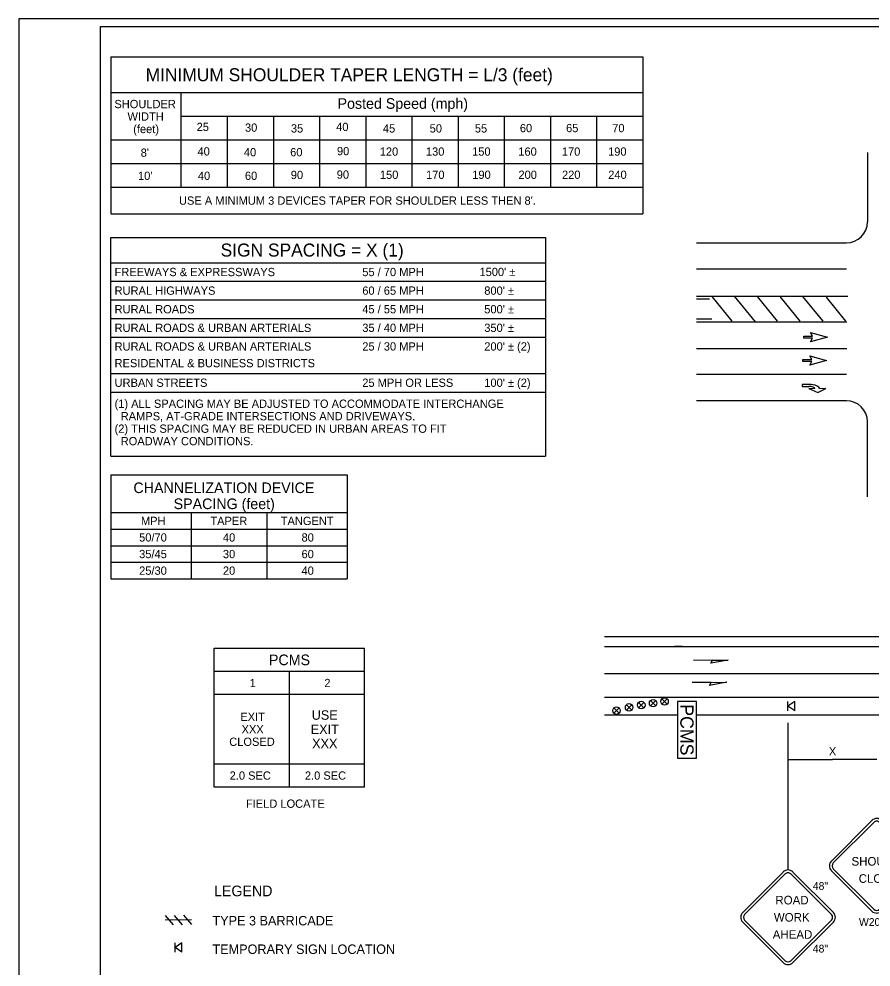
# Model space of a CAD drawing. Extents: x 99988 to 100172, y 99995 to 100047.
# Drawn here: x 99999.31 to 100006.52, y 100002.41 to 100010.44 of the extents above; entities that cross this region are included whole.
import ezdxf

# ---------------------------------------------------------------- set-up
doc = ezdxf.new("R2010")
doc.units = 0
for name, color, linetype in [('Default', 7, 'Continuous'), ('Level 15', 7, 'Continuous'), ('Level 20', 7, 'Continuous'), ('RD_MK_TrafficArrowType1SNew', 7, 'Continuous'), ('RD_MK_TrafficArrowType2RNew', 7, 'Continuous'), ('SH_DE_DetailBody1Text', 7, 'Continuous'), ('SH_DE_DetailHeading2Text', 7, 'Continuous'), ('SH_GI_PlotLimits', 7, 'Continuous'), ('SH_GI_SheetBorder', 7, 'Continuous'), ('SH_GI_TrafficMvmntArrowRt1Lane', 7, 'Continuous'), ('SH_TI_ChanSpacing25to70Note', 7, 'Continuous'), ('SH_TI_MinTaperLength25to35Note', 7, 'Continuous'), ('SH_TI_SignSpacing35to70Note', 7, 'Continuous'), ('TR_SN_WarningSigns', 7, 'Continuous'), ('TR_WZ_BarricadeType3', 7, 'Continuous'), ('TR_WZ_PortableChangeMessageSign', 7, 'Continuous'), ('TR_WZ_WorkZoneDetails', 7, 'Continuous')]:
    doc.layers.add(name, color=color, linetype=linetype)

# ---------------------------------------------------------------- blocks, each defined once
blk = doc.blocks.new('W20-301')
at = {"layer": 'TR_SN_WarningSigns'}
for p, q in [((-0.511, 0.688), (-0.054, 1.145)), ((-0.49, 0.666), (-0.033, 1.123)), ((0.033, 1.123), (0.49, 0.666)), ((0.054, 1.145), (0.511, 0.688)), ((-0.054, 0.123), (-0.511, 0.579)), ((-0.033, 0.144), (-0.49, 0.601)), ((0.49, 0.601), (0.033, 0.144)), ((0.511, 0.579), (0.054, 0.123))]:
    blk.add_line(p, q, dxfattribs=at)
for centre, radius, start, end in [((0, 1.091), 0.0769, 44.9963, 134.9997), ((0, 1.091), 0.0462, 44.9963, 134.9997), ((-0.457, 0.634), 0.0769, 134.9966, 224.9936), ((-0.457, 0.634), 0.0462, 134.9966, 224.9936), ((0.457, 0.634), 0.0462, 314.9994, 44.9948), ((0.457, 0.634), 0.0769, 314.9994, 44.9948), ((0, 0.177), 0.0769, 225, 314.9996), ((0, 0.177), 0.0462, 225, 314.9996)]:
    blk.add_arc(centre, radius, start, end, dxfattribs=at)
for s, height, p in [('48"', 0.0848, (0.282, 0.945)), ('SHOULDER', 0.0969, (-0.284, 0.636)), ('CLOSED', 0.0969, (-0.203, 0.442)), ('48"', 0.0848, (0.282, 0.238)), ('W20-301', 0.0875, (-0.2, -0.044))]:
    blk.add_text(s, height=height, dxfattribs=at).set_placement(p)

msp = doc.modelspace()

# ---------------------------------------------------------------- linework, layer by layer
at = {"layer": 'Default'}
for p, q in [((100004.2658, 100004.8971), (100015.1319, 100004.8971)), ((100004.7968, 100004.6379), (100004.7516, 100004.6831)), ((100004.7968, 100004.6831), (100004.7516, 100004.6379)), ((100004.3903, 100004.5605), (100004.345, 100004.6057)), ((100004.3903, 100004.6057), (100004.345, 100004.5605)), ((100004.4973, 100004.5874), (100004.452, 100004.6327)), ((100004.4973, 100004.6327), (100004.452, 100004.5874)), ((100004.5995, 100004.6076), (100004.5543, 100004.6529)), ((100004.5995, 100004.6529), (100004.5543, 100004.6076)), ((100004.7003, 100004.6235), (100004.6551, 100004.6687)), ((100004.7003, 100004.6687), (100004.6551, 100004.6235)), ((100005.8761, 100004.6609), (100005.8183, 100004.6206)), ((100005.8183, 100004.5804), (100005.8183, 100004.6609)), ((100005.8761, 100004.5804), (100005.8183, 100004.6206)), ((100005.8761, 100004.5804), (100005.8761, 100004.6609)), ((100000.6909, 100002.6181), (100000.6331, 100002.5778)), ((100000.6331, 100002.5376), (100000.6331, 100002.6181)), ((100000.6909, 100002.5376), (100000.6909, 100002.6181)), ((100000.6909, 100002.5376), (100000.6331, 100002.5778))]:
    msp.add_line(p, q, dxfattribs=at)
for centre in [(100004.6777, 100004.6461), (100004.7742, 100004.6605), (100004.3677, 100004.5831), (100004.4746, 100004.6101), (100004.5769, 100004.6302)]:
    msp.add_circle(centre, 0.032, dxfattribs=at)
at = {"layer": 'Level 15'}
for p in [(100005.819, 100004.1687), (100006.569, 100004.1687)]:
    msp.add_line(p, (100006.194, 100004.1687), dxfattribs=at)
at = {"layer": 'RD_MK_TrafficArrowType1SNew'}
for points in [[(100005.9514, 100007.7523), (100006.0264, 100007.7523), (100006.0097, 100007.7835), (100006.1514, 100007.744), (100006.0097, 100007.7044), (100006.0264, 100007.7356), (100005.9514, 100007.7356)], [(100005.9443, 100007.5545), (100006.0193, 100007.5545), (100006.0026, 100007.5857), (100006.1443, 100007.5462), (100006.0026, 100007.5066), (100006.0193, 100007.5378), (100005.9443, 100007.5378)]]:
    msp.add_lwpolyline(points, close=True, dxfattribs=at)
at = {"layer": 'RD_MK_TrafficArrowType2RNew'}
msp.add_line((100005.9958, 100007.3435), (100005.9958, 100007.3435), dxfattribs=at)
for points in [[(100005.9958, 100007.3435), (100005.9374, 100007.3435), (100005.9374, 100007.3268), (100005.9958, 100007.3268)], [(100006.0458, 100007.306), (100005.9958, 100007.3102), (100006.0708, 100007.2768), (100006.1374, 100007.3102), (100006.0874, 100007.306)]]:
    msp.add_lwpolyline(points, dxfattribs=at)
for major_axis, ratio, end_param in [((0.0917, 0), 0.40879, 1.570662), ((0.05, 0), 0.41611, 1.570668)]:
    msp.add_ellipse((100005.9958, 100007.306), major_axis=major_axis, ratio=ratio, start_param=0, end_param=end_param, dxfattribs=at)
at = {"layer": 'SH_GI_PlotLimits'}
msp.add_lwpolyline([(99999.3125, 99999.9375), (100015.8125, 99999.9375), (100015.8125, 100010.4375), (99999.3125, 100010.4375)], close=True, dxfattribs=at)
at = {"layer": 'SH_GI_SheetBorder'}
for q in [(100000, 100000), (100015.75, 100010.375)]:
    msp.add_line((100000, 100010.375), q, dxfattribs=at)
at = {"layer": 'SH_GI_TrafficMvmntArrowRt1Lane'}
for p, q in [((100005.1801, 100005.0095), (100005.0194, 100005.0074)), ((100005.1691, 100004.8221), (100005.0084, 100004.82))]:
    msp.add_line(p, q, dxfattribs=at)
for points in [[(100005.3111, 100005.0113), (100005.1656, 100004.9836), (100005.1801, 100005.0095)], [(100005.3001, 100004.8239), (100005.1546, 100004.7962), (100005.1691, 100004.8221)]]:
    msp.add_lwpolyline(points, close=True, dxfattribs=at)
at = {"layer": 'SH_TI_ChanSpacing25to70Note'}
for p, q in [((100000.0888, 100006.5798), (100000.0888, 100005.6977)), ((100000.0888, 100006.5798), (100002.0888, 100006.5798)), ((100002.0888, 100006.5798), (100002.0888, 100005.6977)), ((100000.0888, 100006.2592), (100002.0888, 100006.2592)), ((100000.7714, 100005.6977), (100000.7714, 100006.2592)), ((100001.4135, 100005.6977), (100001.4135, 100006.2592)), ((100000.0888, 100006.1188), (100002.0888, 100006.1188)), ((100000.0888, 100005.9785), (100002.0888, 100005.9785)), ((100000.0888, 100005.8381), (100002.0888, 100005.8381)), ((100000.0888, 100005.6977), (100002.0888, 100005.6977))]:
    msp.add_line(p, q, dxfattribs=at)
at = {"layer": 'SH_TI_MinTaperLength25to35Note'}
for p, q in [((100000.0904, 100010.1177), (100004.5904, 100010.1177)), ((100000.0904, 100010.1177), (100000.0904, 100009.4074)), ((100004.5904, 100010.1177), (100004.5904, 100009.4074)), ((100000.0904, 100009.8145), (100004.5904, 100009.8145)), ((100000.6835, 100009.4074), (100000.6835, 100009.8145)), ((100000.6835, 100009.6145), (100004.5904, 100009.6145)), ((100001.0742, 100009.6145), (100001.0742, 100009.4074)), ((100001.4649, 100009.6145), (100001.4649, 100009.4074)), ((100001.8556, 100009.6145), (100001.8556, 100009.4074)), ((100002.2463, 100009.6145), (100002.2463, 100009.4074)), ((100002.637, 100009.6145), (100002.637, 100009.4074)), ((100003.0277, 100009.6145), (100003.0277, 100009.4074)), ((100003.4183, 100009.6145), (100003.4183, 100009.4074)), ((100003.809, 100009.6145), (100003.809, 100009.4074)), ((100004.1996, 100009.6145), (100004.1996, 100009.4074)), ((100000.0904, 100009.4145), (100004.5904, 100009.4145)), ((100000.0904, 100009.4074), (100000.0904, 100008.7876)), ((100000.6835, 100009.0128), (100000.6835, 100009.4074)), ((100001.0742, 100009.4074), (100001.0742, 100009.0128)), ((100001.4649, 100009.4074), (100001.4649, 100009.0128)), ((100001.8556, 100009.4074), (100001.8556, 100009.0128)), ((100002.2463, 100009.4074), (100002.2463, 100009.0128)), ((100002.637, 100009.4074), (100002.637, 100009.0128)), ((100003.0277, 100009.4074), (100003.0277, 100009.0128)), ((100003.4183, 100009.4074), (100003.4183, 100009.0128)), ((100003.809, 100009.4074), (100003.809, 100009.0128)), ((100004.1996, 100009.4074), (100004.1996, 100009.0128)), ((100004.5904, 100009.4074), (100004.5904, 100008.7876)), ((100000.0904, 100009.2128), (100004.5904, 100009.2128)), ((100000.0904, 100009.0128), (100004.5904, 100009.0128)), ((100000.0904, 100008.7876), (100004.5904, 100008.7876))]:
    msp.add_line(p, q, dxfattribs=at)
at = {"layer": 'SH_TI_SignSpacing35to70Note'}
for p, q in [((100000.0904, 100008.3742), (100003.7659, 100008.3742)), ((100000.0904, 100008.2167), (100003.7659, 100008.2167)), ((100000.0904, 100008.0593), (100003.7659, 100008.0593)), ((100000.0904, 100007.9019), (100003.7659, 100007.9019)), ((100000.0904, 100007.7445), (100003.7659, 100007.7445)), ((100000.0904, 100007.4371), (100003.7659, 100007.4371)), ((100000.0904, 100007.2797), (100003.7659, 100007.2797)), ((100000.0904, 100006.736), (100003.7659, 100006.736))]:
    msp.add_line(p, q, dxfattribs=at)
msp.add_lwpolyline([(100000.0904, 100006.736), (100000.0904, 100008.5887), (100003.7659, 100008.5887), (100003.7659, 100006.736)], dxfattribs=at)
at = {"layer": 'TR_SN_WarningSigns'}
for p, q in [((100005.4355, 100002.8742), (100005.7782, 100003.2168)), ((100005.4519, 100002.8579), (100005.7945, 100003.2005)), ((100005.8435, 100003.2005), (100006.1862, 100002.8578)), ((100005.8598, 100003.2168), (100006.2025, 100002.8742)), ((100005.7782, 100002.4499), (100005.4355, 100002.7926)), ((100005.7945, 100002.4662), (100005.4519, 100002.8089)), ((100006.1862, 100002.8089), (100005.8435, 100002.4662)), ((100006.2025, 100002.7926), (100005.8598, 100002.4499))]:
    msp.add_line(p, q, dxfattribs=at)
for centre, radius, start, end in [((100005.819, 100003.1761), 0.0577, 44.99628, 134.99965), ((100005.819, 100003.1761), 0.0346, 44.99628, 134.99965), ((100005.4763, 100002.8334), 0.0577, 134.99658, 224.99358), ((100005.4763, 100002.8334), 0.0346, 134.99658, 224.99358), ((100006.1617, 100002.8334), 0.0346, 314.99936, 44.99485), ((100006.1617, 100002.8334), 0.0577, 314.99936, 44.99485), ((100005.819, 100002.4907), 0.0577, 225, 314.99958), ((100005.819, 100002.4907), 0.0346, 225, 314.99958)]:
    msp.add_arc(centre, radius, start, end, dxfattribs=at)
at = {"layer": 'TR_WZ_BarricadeType3'}
for p, q in [((100000.5483, 100002.849), (100000.6158, 100002.7703)), ((100000.6268, 100002.8496), (100000.6943, 100002.7709)), ((100000.7053, 100002.8503), (100000.7728, 100002.7716)), ((100000.7725, 100002.8112), (100000.5487, 100002.8093))]:
    msp.add_line(p, q, dxfattribs=at)
at = {"layer": 'TR_WZ_PortableChangeMessageSign'}
msp.add_lwpolyline([(100004.8836, 100004.6608), (100004.8836, 100004.1808), (100005.0436, 100004.1808), (100005.0436, 100004.6608)], close=True, dxfattribs=at)
at = {"layer": 'TR_WZ_WorkZoneDetails'}
for p, q in [((100006.4912, 100009.3085), (100006.4912, 100008.7205)), ((100005.0448, 100008.5417), (100006.3124, 100008.5417)), ((100006.3124, 100008.32), (100005.0448, 100008.32)), ((100006.017, 100008.089), (100005.0448, 100008.089)), ((100005.1558, 100008.0659), (100005.0448, 100008.0659)), ((100005.1736, 100008.0872), (100005.3426, 100007.8804)), ((100005.3632, 100008.0907), (100005.541, 100007.8729)), ((100005.5568, 100008.0892), (100005.7274, 100007.8804)), ((100005.749, 100008.0895), (100005.9197, 100007.8804)), ((100005.9419, 100008.0889), (100006.1121, 100007.8804)), ((100006.3239, 100008.089), (100006.017, 100008.089)), ((100006.1402, 100008.0815), (100006.3045, 100007.8804)), ((100005.1752, 100007.8957), (100005.0448, 100007.8957)), ((100005.0448, 100007.8729), (100006.3159, 100007.8729)), ((100005.0448, 100007.6494), (100006.3159, 100007.6494)), ((100006.3124, 100007.4277), (100005.0448, 100007.4277)), ((100006.3124, 100007.206), (100005.0448, 100007.206)), ((100006.4912, 100006.3918), (100006.4912, 100007.0272)), ((100004.2658, 100005.2089), (100015.1308, 100005.2089)), ((100000.964, 100005.1105), (100002.2371, 100005.1105)), ((100000.964, 100003.9353), (100000.964, 100005.1105)), ((100002.2371, 100003.9353), (100002.2371, 100005.1105)), ((100004.2658, 100005.1256), (100015.1308, 100005.1256)), ((100004.9223, 100005.1256), (100004.8592, 100005.1256)), ((100002.2371, 100004.9146), (100000.964, 100004.9146)), ((100001.6006, 100003.9353), (100001.6006, 100004.9146)), ((100002.2371, 100004.7188), (100000.964, 100004.7188)), ((100004.2658, 100004.6961), (100009.937, 100004.6961)), ((100004.2658, 100004.5463), (100004.8819, 100004.5463)), ((100005.0504, 100004.5463), (100011.3395, 100004.5463)), ((100005.819, 100003.2337), (100005.819, 100004.4804)), ((100000.964, 100004.1311), (100002.2371, 100004.1311)), ((100002.2371, 100003.9353), (100000.964, 100003.9353))]:
    msp.add_line(p, q, dxfattribs=at)
for centre, start, end in [((100006.3124, 100008.7205), 270, 0), ((100006.3124, 100007.0273), 0, 90)]:
    msp.add_arc(centre, 0.1788, start, end, dxfattribs=at)

# ---------------------------------------------------------------- block references
at = {"layer": 'TR_WZ_WorkZoneDetails', "xscale": 0.7500000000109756, "yscale": 0.7500000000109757}
msp.add_blockref('W20-301', (100006.569, 100002.7937), dxfattribs=at)

# ---------------------------------------------------------------- texts
at = {"layer": 'Level 20'}
msp.add_text('X', height=0.07, rotation=360, dxfattribs=at).set_placement((100006.1643, 100004.2037))
at = {"layer": 'SH_DE_DetailBody1Text'}
for s, height, p in [('PCMS', 0.09, (100001.4272, 100004.9676)), ('1', 0.07, (100001.2643, 100004.7817)), ('2', 0.07, (100001.8962, 100004.7817)), ('EXIT', 0.07, (100001.1852, 100004.4955)), ('USE', 0.08, (100001.7891, 100004.5056)), ('XXX', 0.07, (100001.1958, 100004.3899)), ('EXIT', 0.08, (100001.7808, 100004.3849)), ('CLOSED', 0.07, (100001.0915, 100004.2844)), ('XXX', 0.08, (100001.7928, 100004.2643)), ('2.0 SEC', 0.07, (100001.0949, 100003.9982)), ('2.0 SEC', 0.07, (100001.7315, 100003.9982)), ('FIELD LOCATE', 0.07, (100001.2329, 100003.7603)), ('TYPE 3 BARRICADE', 0.08, (100000.9494, 100002.7647)), ('TEMPORARY SIGN LOCATION', 0.08, (100000.9494, 100002.5234))]:
    msp.add_text(s, height=height, dxfattribs=at).set_placement(p)
at = {"layer": 'SH_DE_DetailHeading2Text'}
msp.add_text('LEGEND', height=0.09, dxfattribs=at).set_placement((100000.9626, 100003.0115))
at = {"layer": 'SH_TI_ChanSpacing25to70Note'}
for s, height, p in [('CHANNELIZATION DEVICE', 0.09, (100000.2808, 100006.4242)), ('SPACING (feet)', 0.09, (100000.6211, 100006.2885)), ('MPH', 0.07, (100000.3445, 100006.154)), ('TAPER', 0.07, (100000.9317, 100006.154)), ('TANGENT', 0.07, (100001.5274, 100006.154)), ('50/70', 0.07, (100000.3292, 100006.0137)), ('40', 0.07, (100001.0379, 100006.0137)), ('80', 0.07, (100001.703, 100006.0137)), ('35/45', 0.07, (100000.3292, 100005.8733)), ('30', 0.07, (100001.0379, 100005.8733)), ('60', 0.07, (100001.703, 100005.8733)), ('25/30', 0.07, (100000.3292, 100005.7329)), ('20', 0.07, (100001.0379, 100005.7329)), ('40', 0.07, (100001.703, 100005.7329))]:
    msp.add_text(s, height=height, dxfattribs=at).set_placement(p)
at = {"layer": 'SH_TI_MinTaperLength25to35Note'}
for s, height, p in [('MINIMUM SHOULDER TAPER LENGTH = L/3 (feet)', 0.11, (100000.3841, 100009.9101)), ('SHOULDER', 0.07, (100000.1198, 100009.6824)), ('Posted Speed (mph)', 0.09, (100002.0079, 100009.6769)), ('WIDTH', 0.07, (100000.2307, 100009.5768)), ('(feet)', 0.07, (100000.2788, 100009.4712)), ('25', 0.07, (100000.8157, 100009.489)), ('30', 0.07, (100001.2247, 100009.4828)), ('35', 0.07, (100001.6132, 100009.4762)), ('40', 0.07, (100001.9961, 100009.489)), ('45', 0.07, (100002.3915, 100009.4762)), ('50', 0.07, (100002.7871, 100009.4762)), ('55', 0.07, (100003.1694, 100009.4762)), ('60', 0.07, (100003.5502, 100009.479)), ('65', 0.07, (100003.9409, 100009.479)), ('70', 0.07, (100004.3316, 100009.479)), ("8'", 0.07, (100000.3424, 100009.2711)), ('40', 0.07, (100000.8232, 100009.2815)), ('40', 0.07, (100001.2153, 100009.2749)), ('60', 0.07, (100001.6069, 100009.2749)), ('90', 0.07, (100002.0027, 100009.2841)), ('120', 0.07, (100002.3647, 100009.2801)), ('130', 0.07, (100002.7554, 100009.2801)), ('150', 0.07, (100003.1461, 100009.2801)), ('160', 0.07, (100003.5368, 100009.2801)), ('170', 0.07, (100003.9055, 100009.2801)), ('190', 0.07, (100004.2965, 100009.2801)), ("10'", 0.07, (100000.3196, 100009.0751)), ('40', 0.07, (100000.8261, 100009.0751)), ('60', 0.07, (100001.224, 100009.0751)), ('90', 0.07, (100001.6124, 100009.0822)), ('90', 0.07, (100002.001, 100009.0854)), ('150', 0.07, (100002.3659, 100009.0837)), ('170', 0.07, (100002.7566, 100009.0837)), ('190', 0.07, (100003.1473, 100009.0837)), ('200', 0.07, (100003.538, 100009.0837)), ('220', 0.07, (100003.9067, 100009.0837)), ('240', 0.07, (100004.2977, 100009.0837)), ("USE A MINIMUM 3 DEVICES TAPER FOR SHOULDER LESS THEN 8'.", 0.07, (100000.6663, 100008.865))]:
    msp.add_text(s, height=height, dxfattribs=at).set_placement(p)
at = {"layer": 'SH_TI_SignSpacing35to70Note'}
for s, height, p in [('SIGN SPACING = X (1)', 0.11, (100001.0185, 100008.4264)), ('FREEWAYS & EXPRESSWAYS', 0.07, (100000.1214, 100008.2605)), ('55 / 70 MPH', 0.07, (100002.217, 100008.2605)), ("1500' ±", 0.07, (100003.2086, 100008.2612)), ('RURAL HIGHWAYS', 0.07, (100000.1214, 100008.103)), ('60 / 65 MPH', 0.07, (100002.217, 100008.103)), ("800' ±", 0.07, (100003.249, 100008.103)), ('RURAL ROADS', 0.07, (100000.1214, 100007.9456)), ('45 / 55 MPH', 0.07, (100002.217, 100007.9456)), ("500' ±", 0.07, (100003.249, 100007.9456)), ('RURAL ROADS & URBAN ARTERIALS', 0.07, (100000.1214, 100007.7882)), ('35 / 40 MPH', 0.07, (100002.217, 100007.7882)), ("350' ± ", 0.07, (100003.249, 100007.7882)), ('RURAL ROADS & URBAN ARTERIALS', 0.07, (100000.1214, 100007.6305)), ('25 / 30 MPH', 0.07, (100002.217, 100007.6308)), ("200' ± (2)", 0.07, (100003.249, 100007.6308)), ('RESIDENTAL & BUSINESS DISTRICTS', 0.07, (100000.1214, 100007.4894)), ('URBAN STREETS', 0.07, (100000.1214, 100007.3234)), ('25 MPH OR LESS', 0.07, (100002.217, 100007.3234)), ("100' ± (2) ", 0.07, (100003.249, 100007.3234)), ('(1) ALL SPACING MAY BE ADJUSTED TO ACCOMMODATE INTERCHANGE ', 0.07, (100000.1213, 100007.1457)), ('  RAMPS, AT-GRADE INTERSECTIONS AND DRIVEWAYS.', 0.07, (100000.1213, 100007.0402)), ('(2) THIS SPACING MAY BE REDUCED IN URBAN AREAS TO FIT  ', 0.07, (100000.1213, 100006.9346)), ('  ROADWAY CONDITIONS.', 0.07, (100000.1213, 100006.8291))]:
    msp.add_text(s, height=height, dxfattribs=at).set_placement(p)
at = {"layer": 'TR_SN_WarningSigns'}
for s, height, p in [('48"', 0.06563, (100006.0287, 100003.0657)), ('ROAD', 0.07268, (100005.712, 100002.9424)), ('WORK', 0.07268, (100005.6989, 100002.797)), ('AHEAD', 0.07268, (100005.6893, 100002.6517)), ('48"', 0.06563, (100006.0287, 100002.5354))]:
    msp.add_text(s, height=height, dxfattribs=at).set_placement(p)
at = {"layer": 'TR_WZ_PortableChangeMessageSign'}
msp.add_text('PCMS', height=0.112, rotation=270, dxfattribs=at).set_placement((100004.9076, 100004.6363))

doc.saveas('drawing.dxf')
